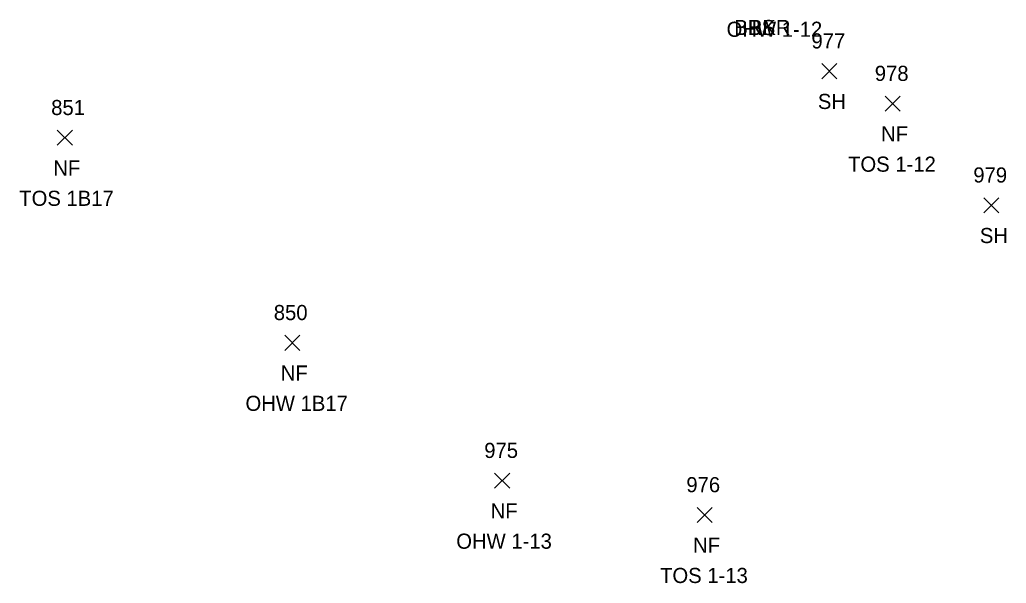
# Model space of a CAD drawing. Extents: x 1528286 to 1556263, y 492387 to 508952.
# Drawn here: x 1528286.7 to 1528417.1, y 492387.2 to 492461.7 of the extents above; entities that cross this region are included whole.
import ezdxf

# ---------------------------------------------------------------- set-up
doc = ezdxf.new("R2010")
doc.units = 0
for name, color, linetype in [('L_A', 7, 'Continuous'), ('L_C', 7, 'Continuous'), ('L_I', 7, 'Continuous'), ('L_TIC', 7, 'Continuous')]:
    doc.layers.add(name, color=color, linetype=linetype)

msp = doc.modelspace()

# ---------------------------------------------------------------- linework, layer by layer
at = {"layer": 'L_TIC'}
for points in [[(1528392.7, 492453.88), (1528394.7, 492455.88)], [(1528394.7, 492453.88), (1528392.7, 492455.88)], [(1528392.7, 492453.88), (1528394.7, 492455.88)], [(1528394.7, 492453.88), (1528392.7, 492455.88)], [(1528401.07, 492449.59), (1528403.07, 492451.59)], [(1528403.07, 492449.59), (1528401.07, 492451.59)], [(1528401.07, 492449.59), (1528403.07, 492451.59)], [(1528403.07, 492449.59), (1528401.07, 492451.59)], [(1528291.69, 492445.08), (1528293.69, 492447.08)], [(1528293.69, 492445.08), (1528291.69, 492447.08)], [(1528291.69, 492445.08), (1528293.69, 492447.08)], [(1528293.69, 492445.08), (1528291.69, 492447.08)], [(1528414.1, 492436.16), (1528416.1, 492438.16)], [(1528416.1, 492436.16), (1528414.1, 492438.16)], [(1528414.1, 492436.16), (1528416.1, 492438.16)], [(1528416.1, 492436.16), (1528414.1, 492438.16)], [(1528321.75, 492417.98), (1528323.75, 492419.98)], [(1528323.75, 492417.98), (1528321.75, 492419.98)], [(1528321.75, 492417.98), (1528323.75, 492419.98)], [(1528323.75, 492417.98), (1528321.75, 492419.98)], [(1528349.47, 492399.76), (1528351.47, 492401.76)], [(1528351.47, 492399.76), (1528349.47, 492401.76)], [(1528349.47, 492399.76), (1528351.47, 492401.76)], [(1528351.47, 492399.76), (1528349.47, 492401.76)], [(1528376.23, 492395.23), (1528378.23, 492397.23)], [(1528378.23, 492395.23), (1528376.23, 492397.23)], [(1528376.23, 492395.23), (1528378.23, 492397.23)], [(1528378.23, 492395.23), (1528376.23, 492397.23)]]:
    msp.add_lwpolyline(points, dxfattribs=at)

# ---------------------------------------------------------------- texts
at = {"layer": 'L_A'}
for s, p in [('BRKR', (1528381.14, 492459.65)), ('BRKR', (1528381.14, 492459.65)), ('BS', (1528382.99, 492459.65)), ('BS', (1528382.99, 492459.65)), ('SH', (1528392.19, 492449.88)), ('SH', (1528392.19, 492449.88)), ('NF', (1528400.55, 492445.59)), ('NF', (1528400.55, 492445.59)), ('NF', (1528291.17, 492441.08)), ('NF', (1528291.17, 492441.08)), ('SH', (1528413.59, 492432.16)), ('SH', (1528413.59, 492432.16)), ('NF', (1528321.23, 492413.98)), ('NF', (1528321.23, 492413.98)), ('NF', (1528348.95, 492395.76)), ('NF', (1528348.95, 492395.76)), ('NF', (1528375.71, 492391.23)), ('NF', (1528375.71, 492391.23))]:
    msp.add_text(s, height=2, dxfattribs=at).set_placement(p)
at = {"layer": 'L_C'}
for s, p in [('OHW 1-12', (1528380.13, 492459.42)), ('OHW 1-12', (1528380.13, 492459.42)), ('TOS 1-12', (1528396.18, 492441.59)), ('TOS 1-12', (1528396.18, 492441.59)), ('TOS 1B17', (1528286.67, 492437.08)), ('TOS 1B17', (1528286.67, 492437.08)), ('OHW 1B17', (1528316.56, 492409.98)), ('OHW 1B17', (1528316.56, 492409.98)), ('OHW 1-13', (1528344.41, 492391.76)), ('OHW 1-13', (1528344.41, 492391.76)), ('TOS 1-13', (1528371.34, 492387.23)), ('TOS 1-13', (1528371.34, 492387.23))]:
    msp.add_text(s, height=2, dxfattribs=at).set_placement(p)
at = {"layer": 'L_I'}
for s, p in [('977', (1528391.34, 492457.88)), ('977', (1528391.34, 492457.88)), ('978', (1528399.71, 492453.59)), ('978', (1528399.71, 492453.59)), ('851', (1528290.89, 492449.08)), ('851', (1528290.89, 492449.08)), ('979', (1528412.73, 492440.16)), ('979', (1528412.73, 492440.16)), ('850', (1528320.3, 492421.98)), ('850', (1528320.3, 492421.98)), ('975', (1528348.11, 492403.76)), ('975', (1528348.11, 492403.76)), ('976', (1528374.81, 492399.23)), ('976', (1528374.81, 492399.23))]:
    msp.add_text(s, height=2, dxfattribs=at).set_placement(p)

doc.saveas('drawing.dxf')
